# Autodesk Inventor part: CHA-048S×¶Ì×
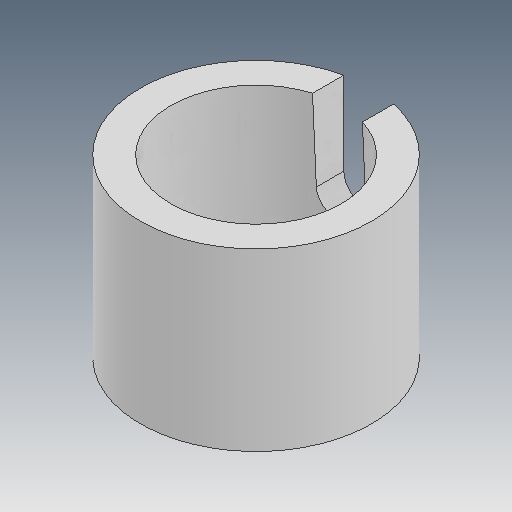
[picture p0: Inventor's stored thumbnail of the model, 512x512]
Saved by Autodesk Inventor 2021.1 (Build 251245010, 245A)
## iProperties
Created: 2019-05
Part Number: CHA-048S×¶Ì×
Material: Ogólny
Document SubType Name: Modeling
Designer: user
Density: 1 g/cm^3
Appearance: Domyślna
Author: user
Revision Number: ÈÎºÎ
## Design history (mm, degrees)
feature "ÊäÈë1"
node "Bryła1"
